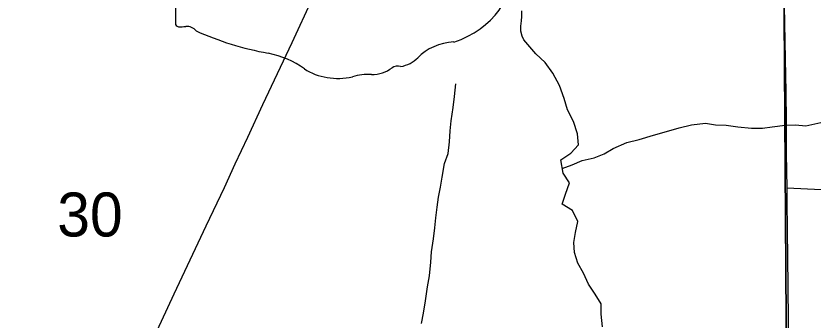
# Model space of a CAD drawing. Extents: x 0 to 34, y 0 to 22.
# Drawn here: x 6.195 to 6.953, y 16.614 to 16.904 of the extents above; entities that cross this region are included whole.
import ezdxf

# ---------------------------------------------------------------- set-up
doc = ezdxf.new("R2010")
doc.units = 0
for name, color, linetype in [('GM_X_Minor_River', 7, 'Continuous'), ('GM_X_Section', 7, 'Continuous'), ('GM_X_Section_Text', 7, 'Continuous'), ('GM_X_State_Route', 7, 'Continuous'), ('GM_X_State_Shield', 7, 'Continuous'), ('GM_X_Township_Road', 7, 'Continuous')]:
    doc.layers.add(name, color=color, linetype=linetype)

msp = doc.modelspace()

# ---------------------------------------------------------------- linework, layer by layer
at = {"layer": 'GM_X_Minor_River'}
for points in [[(6.67834, 16.88115), (6.67651, 16.88478), (6.67531, 16.88932), (6.67524, 16.89426), (6.67594, 16.89921), (6.67626, 16.90339), (6.67619, 16.9087)], [(6.7293, 16.79181), (6.72557, 16.80359), (6.71994, 16.81462), (6.71657, 16.82526), (6.71209, 16.83781), (6.7057, 16.8496), (6.69856, 16.8595), (6.68951, 16.86789), (6.67834, 16.88115)], [(6.58076, 16.61116), (6.58269, 16.62102), (6.58463, 16.63277), (6.58657, 16.64604), (6.5885, 16.65666), (6.58968, 16.66955), (6.59048, 16.67941), (6.59241, 16.69193), (6.59359, 16.70216), (6.59438, 16.71165), (6.59593, 16.72188), (6.5971, 16.73136), (6.59903, 16.74084), (6.60058, 16.75032), (6.6029, 16.76359), (6.60634, 16.77306), (6.60751, 16.78406), (6.60831, 16.79468), (6.6091, 16.80416), (6.61104, 16.81667), (6.61222, 16.82729), (6.6134, 16.83943)], [(6.71476, 16.75876), (6.72428, 16.76224), (6.73374, 16.76637), (6.7451, 16.76897), (6.75457, 16.77271), (6.76328, 16.77761), (6.77616, 16.78361), (6.78789, 16.78621), (6.80152, 16.79032), (6.81402, 16.79406), (6.82613, 16.79741), (6.83786, 16.80039), (6.8511, 16.80184), (6.86055, 16.80028), (6.87076, 16.79985), (6.88172, 16.79828), (6.89495, 16.79708), (6.90516, 16.79703), (6.91462, 16.7985), (6.92672, 16.79996), (6.93656, 16.80029), (6.94638, 16.79948), (6.96076, 16.80245)], [(6.75318, 16.60804), (6.75171, 16.62019), (6.75175, 16.63006), (6.74611, 16.63919), (6.73972, 16.64871), (6.73485, 16.65898), (6.72959, 16.66849), (6.7266, 16.67875), (6.72588, 16.68824), (6.72743, 16.69772), (6.72974, 16.70833), (6.72449, 16.7186), (6.71468, 16.72472), (6.71774, 16.73419), (6.72156, 16.74518), (6.71555, 16.75431), (6.71333, 16.76685), (6.72281, 16.77325), (6.7304, 16.78118), (6.7293, 16.79181)]]:
    msp.add_lwpolyline(points, dxfattribs=at)
at = {"layer": 'GM_X_Section'}
for points in [[(6.92373, 17.24282), (7.92008, 17.25434), (7.92004, 16.95796), (7.93409, 16.26707), (7.50296, 16.23822), (6.93034, 16.22819)], [(5.77238, 17.22806), (6.92373, 17.24282), (6.93034, 16.22819), (5.7699, 16.21486), (5.77176, 16.27968)]]:
    msp.add_lwpolyline(points, close=True, dxfattribs=at)
at = {"layer": 'GM_X_State_Route'}
msp.add_lwpolyline([(6.17944, 16.28502), (6.22173, 16.37495), (6.25741, 16.45074), (6.25985, 16.45596), (6.29688, 16.53524), (6.32333, 16.59149), (6.34552, 16.63945), (6.37593, 16.70416), (6.39336, 16.74061), (6.40361, 16.76327), (6.41563, 16.78851), (6.43004, 16.81953), (6.45784, 16.87857), (6.47731, 16.92093), (6.50798, 16.98598)], dxfattribs=at)
at = {"layer": 'GM_X_State_Shield'}
msp.add_line((6.34676, 17.09722), (6.34676, 16.8971), dxfattribs=at)
for centre, major_axis, start_param, end_param in [((6.57852, 16.94381), (0.08742, 0), 5.101752, 6.440018), ((6.35057, 16.89666), (0.00385, 0), 3.00124, 4.508301), ((6.35115, 16.91713), (0.0294, 0), 4.665946, 4.897461), ((6.35716, 16.88555), (0.0106, 0), 0.519207, 1.627899), ((6.49099, 17.06535), (0.2524, 0), 4.195997, 4.488961), ((6.61538, 16.84092), (0.04788, 0), 1.647645, 2.488434), ((6.41574, 16.80719), (0.07897, 0), 0.823519, 1.323587), ((6.55472, 16.8777), (0.02824, 0), 4.937069, 5.64225), ((6.50115, 16.88456), (0.05011, 0), 4.026481, 4.996735), ((6.53377, 16.86957), (0.0267, 0), 4.691044, 5.507374), ((6.55792, 16.85019), (0.00752, 0), 1.147584, 2.315152), ((6.53011, 16.81537), (0.04118, 0), 1.495662, 1.94098)]:
    msp.add_ellipse(centre, major_axis=major_axis, ratio=0.8, start_param=start_param, end_param=end_param, dxfattribs=at)
at = {"layer": 'GM_X_Township_Road'}
for points in [[(6.9287, 16.74018), (6.92829, 16.77277), (6.92809, 16.80382), (6.92781, 16.83177), (6.92729, 16.8627), (6.9265, 16.89681), (6.92581, 16.93097)], [(6.92891, 15.99286), (6.92904, 15.99802), (6.92992, 16.0477), (6.93074, 16.08497), (6.93112, 16.1098), (6.93131, 16.13463), (6.93154, 16.15947), (6.93166, 16.19676), (6.93205, 16.2651), (6.93189, 16.3117), (6.93147, 16.35519), (6.93114, 16.38314), (6.93109, 16.42662), (6.93095, 16.4639), (6.93063, 16.50429), (6.93001, 16.56641), (6.93016, 16.61301), (6.9296, 16.64718), (6.92914, 16.69998), (6.92875, 16.72791), (6.9287, 16.74018)], [(6.9287, 16.74018), (6.9741, 16.73815), (7.01761, 16.73645), (7.04285, 16.73542), (7.0565, 16.73488), (7.06964, 16.73437), (7.09301, 16.7335), (7.11125, 16.73282), (7.13302, 16.73201)]]:
    msp.add_lwpolyline(points, dxfattribs=at)

# ---------------------------------------------------------------- texts
at = {"layer": 'GM_X_Section_Text'}
msp.add_text('30', height=0.041856, rotation=0.00001, dxfattribs=at).set_placement((6.23432, 16.69402))

doc.saveas('drawing.dxf')
